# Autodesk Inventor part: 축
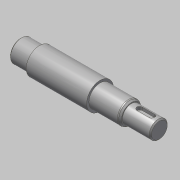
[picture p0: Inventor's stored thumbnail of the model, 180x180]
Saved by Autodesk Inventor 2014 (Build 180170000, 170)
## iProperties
Created: 2016-06
Part Number: 축
Material: 강철, 연강
Document SubType Name: Modeling
Designer: mduedu
Density: 7.86 g/cm^3
Appearance: Steel
Author: mduedu
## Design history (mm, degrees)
sketch "스케치1"
  geometry: L1 (-62, 0)-(62, 0); L2 (-62, 0)-(-62, 10); L3 (-62, 10)-(-45, 10); L4 (-45, 10)-(-45, 12); L5 (-45, 12)-(9, 12); L6 (9, 12)-(9, 10); L7 (9, 10)-(37, 10); L8 (37, 10)-(37, 8); L9 (37, 8)-(62, 8); L10 (62, 8)-(62, 0); 2 further points
  constraints: 20 end point, 5 parallel, 2 perpendicular, 1 coincident, 1 collinear, 1 horizontal, 1 midpoint, 1 vertical
  dimensions: "d0" = 124 distance of L1.start L1.end; "d2" = 16 diameter of L9 L1; "d3" = 20 diameter of L7 L1; "d4" = 24 diameter of L5 L1; "d5" = 20 diameter of L3 L1; "d6" = 17 distance of L2.end L3.end; "d7" = 25 distance of L8.end L9.end; "d8" = 53 distance from line of L5.end L10
revolve "회전1" sketch "스케치1" stored, may be unused: angle "d9" = 90 deg
chamfer "모따기1" distance "d10" = 2; stored, may be unused: second distance "d11" = 2, angle "d12" = 30 deg
fillet "모깎기1" dims "d13" = 2
node "작업 평면1"
sketch "스케치2"
  geometry: L1 (-5, 2.5)-(6, 2.5); L2 (6, -2.5)-(-5, -2.5); L3 (-5, 0)-(6, 0); L4 (-12.5, 8.845)-(-12.5, -8.845) reference; A1 r 2.5 centre (-5, 0) between (-5, 2.5) and (-5, -2.5); A2 r 2.5 centre (6, 0) between (6, -2.5) and (6, 2.5); 1 further point
  constraints: 6 end point, 4 point on circle, 3 tangent, 2 centre point, 2 parallel, 1 horizontal, 1 horizontal alignment
  dimensions: "d14" = 5 distance edge to line of A1 L4; "d15" = 5 distance between parallel lines of L2 L1; "d16" = 16 dimension on A2 A1
extrude "돌출1" cut sketch "스케치2" distance "d17" = 3; taper "d18" = 0 deg
chamfer "모따기2" distance "d19" = 1; stored, may be unused: second distance "d20" = 2, angle "d21" = 30 deg
sketch "스케치3"
  geometry: L1 (-37, -8)-(-61, -8) reference; L2 (-62, -7)-(-62, 7) reference; L3 (-38.5, -8)-(-40, -6.5); L4 (-40, -6.5)-(-40, -8); L5 (-38.5, -8)-(-40, -8); 1 further point
  constraints: 6 end point, 2 point on line, 1 collinear, 1 vertical
  dimensions: "d22" = 45 deg angle of L4 L3; "d23" = 22 distance between parallel lines of L2 L4; "d24" = 3 diameter of L3.start L4
revolve "회전2" stored, may be unused: angle "d25" = 90 deg
node "작업점1"
sketch "스케치4"
  geometry: 1 further point
hole "구멍1" sketch "스케치4" at (0, 0) diameter "d26" = 3.242; stored, may be unused: countersink angle "d30" = 90 deg, drill point angle "d32" = 120 deg; dims "d27" = 8, "d28" = 4, "d29" = 2, "d31" = 11
chamfer "모따기3" distance "d33" = 2; stored, may be unused: second distance "d34" = 2, angle "d35" = 30 deg
node "솔리드1"
